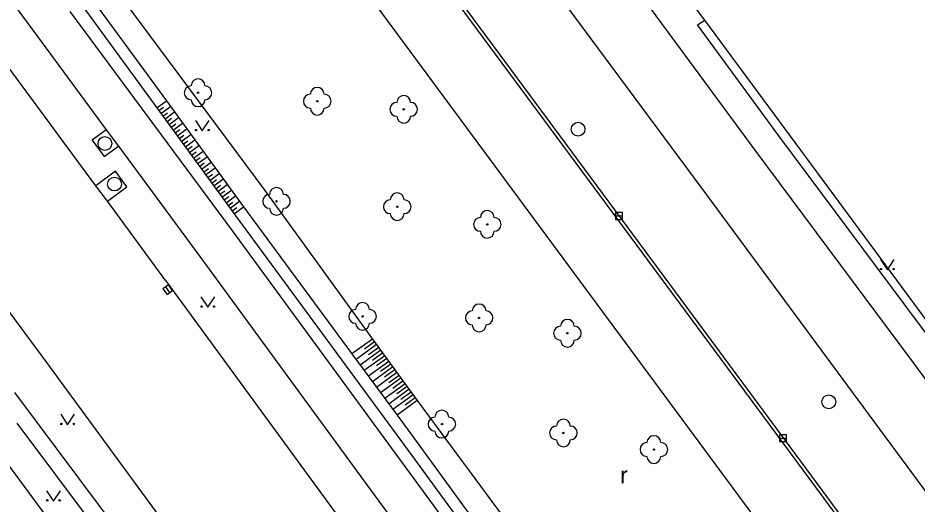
# Model space of a CAD drawing. Extents: x -596024 to -594475, y -1163820 to -1161957.
# Drawn here: x -594574.3 to -594509.2, y -1163261.3 to -1163226.1 of the extents above; entities that cross this region are included whole.
import ezdxf

# ---------------------------------------------------------------- set-up
doc = ezdxf.new("R2010")
doc.units = 0
for name, color, linetype in [('Level 10', 7, 'Continuous'), ('Level 11', 7, 'Continuous'), ('Level 14', 7, 'Continuous'), ('Level 15', 7, 'Continuous'), ('Level 22', 7, 'Continuous'), ('Level 27', 7, 'Continuous'), ('Level 36', 7, 'Continuous'), ('Level 5', 7, 'Continuous')]:
    doc.layers.add(name, color=color, linetype=linetype)

msp = doc.modelspace()

# ---------------------------------------------------------------- linework, layer by layer
at = {"layer": 'Level 10'}
for points in [[(-594476.38, -1163295.95), (-594483.21, -1163286.71), (-594496.95, -1163267.99), (-594509.44, -1163251.06), (-594520.92, -1163235.64), (-594534.84, -1163216.72), (-594549.23, -1163197.24), (-594565.49, -1163175.29), (-594578.05, -1163158.33), (-594594.16, -1163136.56), (-594607.21, -1163118.84), (-594619.14, -1163102.72), (-594629.15, -1163089.16), (-594640.89, -1163073.35), (-594644.69, -1163076.23)], [(-594568.65, -1163238.21), (-594575.33, -1163229.15)], [(-594583.7, -1163235.5), (-594572.22, -1163251)], [(-594567.81, -1163239.34), (-594568.65, -1163238.21)], [(-594563.57, -1163245.1), (-594567.81, -1163239.34)], [(-594563.57, -1163245.1), (-594551.26, -1163261.97)], [(-594572.22, -1163251), (-594559.99, -1163267.72)]]:
    msp.add_lwpolyline(points, dxfattribs=at)
at = {"layer": 'Level 11'}
for points in [[(-594658.25, -1163068.41), (-594648.78, -1163081.26), (-594637.52, -1163096.5), (-594627.94, -1163109.39), (-594616.36, -1163125.13), (-594603.5, -1163142.69), (-594587.25, -1163164.52), (-594574.42, -1163181.74), (-594559, -1163202.7), (-594543.73, -1163223.28), (-594530.41, -1163241.31), (-594518.2, -1163257.82), (-594506.57, -1163273.57), (-594492.81, -1163292.25), (-594492.53, -1163292.63), (-594483.61, -1163304.74), (-594481.85, -1163307.13)], [(-594657.91, -1163068.45), (-594648.58, -1163081.11), (-594637.31, -1163096.34), (-594627.74, -1163109.24), (-594616.16, -1163124.98), (-594603.29, -1163142.54), (-594587.04, -1163164.37), (-594574.22, -1163181.58), (-594558.79, -1163202.55), (-594543.52, -1163223.13), (-594530.21, -1163241.16), (-594518, -1163257.67), (-594506.37, -1163273.42), (-594492.33, -1163292.48), (-594481.65, -1163306.98), (-594481.85, -1163307.13)], [(-594496.66, -1163295.08), (-594662.09, -1163071.26)], [(-594480.26, -1163298.73), (-594487.23, -1163289.32), (-594500.98, -1163270.61), (-594513.05, -1163254.27), (-594524.82, -1163238.32), (-594538.75, -1163219.51), (-594553.56, -1163199.46), (-594569.42, -1163177.97), (-594581.93, -1163161.1), (-594598.22, -1163139.15), (-594611.25, -1163121.45), (-594623.1, -1163105.4), (-594630.38, -1163095.55), (-594644.69, -1163076.23)], [(-594584.79, -1163211.27), (-594572.88, -1163227.4)], [(-594570.52, -1163225.59), (-594558.76, -1163241.51)], [(-594502.96, -1163255.47), (-594503.48, -1163255.85), (-594507.9, -1163249.78), (-594519.28, -1163234.5), (-594525.1, -1163226.56), (-594524.57, -1163226.23)], [(-594572.88, -1163227.4), (-594567.89, -1163234.16)], [(-594567.89, -1163234.16), (-594568.91, -1163234.92)], [(-594567.89, -1163234.16), (-594567.02, -1163235.34)], [(-594568.91, -1163234.92), (-594568.05, -1163236.1)], [(-594568.05, -1163236.1), (-594567.02, -1163235.34)], [(-594567.02, -1163235.34), (-594561.12, -1163243.33)], [(-594567.22, -1163237.16), (-594568.65, -1163238.21)], [(-594566.4, -1163238.3), (-594567.22, -1163237.16)], [(-594567.81, -1163239.34), (-594566.4, -1163238.3)], [(-594558.76, -1163241.51), (-594546.73, -1163257.91)], [(-594561.12, -1163243.33), (-594549.02, -1163259.86)], [(-594546.73, -1163257.91), (-594534.76, -1163274.26)], [(-594549.02, -1163259.86), (-594538.3, -1163274.48)]]:
    msp.add_lwpolyline(points, dxfattribs=at)
at = {"layer": 'Level 14'}
for points in [[(-594570.38, -1163222.7), (-594563.54, -1163232.07), (-594557.95, -1163239.74)], [(-594568.3, -1163222.52), (-594556.42, -1163238.56)], [(-594569.79, -1163224.98), (-594564.24, -1163232.57), (-594558.63, -1163240.24)], [(-594556.42, -1163238.56), (-594548.61, -1163249.31), (-594545.38, -1163253.76)], [(-594558.63, -1163240.24), (-594546.04, -1163257.37)], [(-594557.95, -1163239.74), (-594550.11, -1163250.39), (-594546.84, -1163254.82)], [(-594562.25, -1163269.59), (-594574.52, -1163253.19)], [(-594545.38, -1163253.76), (-594532.52, -1163271.16)], [(-594546.84, -1163254.82), (-594545.38, -1163256.81)], [(-594574.36, -1163255.4), (-594563.25, -1163270.27)], [(-594576.23, -1163256.77), (-594565.21, -1163271.72)], [(-594545.38, -1163256.81), (-594538.57, -1163266.18), (-594534.16, -1163272.25)], [(-594546.04, -1163257.37), (-594539.25, -1163266.68), (-594534.83, -1163272.74)]]:
    msp.add_lwpolyline(points, dxfattribs=at)
at = {"layer": 'Level 15'}
for points in [[(-594564.24, -1163232.57), (-594563.54, -1163232.07)], [(-594564.09, -1163232.77), (-594563.74, -1163232.52)], [(-594563.94, -1163232.98), (-594563.25, -1163232.47)], [(-594563.8, -1163233.18), (-594563.45, -1163232.93)], [(-594563.65, -1163233.38), (-594562.95, -1163232.87)], [(-594563.5, -1163233.58), (-594563.16, -1163233.33)], [(-594563.35, -1163233.78), (-594562.66, -1163233.28)], [(-594563.21, -1163233.99), (-594562.86, -1163233.73)], [(-594563.06, -1163234.19), (-594562.37, -1163233.68)], [(-594562.91, -1163234.39), (-594562.56, -1163234.14)], [(-594562.76, -1163234.59), (-594562.07, -1163234.09)], [(-594562.47, -1163235), (-594561.78, -1163234.49)], [(-594562.62, -1163234.79), (-594562.27, -1163234.54)], [(-594562.32, -1163235.2), (-594561.98, -1163234.95)], [(-594562.17, -1163235.4), (-594561.48, -1163234.89)], [(-594562.03, -1163235.6), (-594561.68, -1163235.35)], [(-594561.88, -1163235.8), (-594561.19, -1163235.3)], [(-594561.73, -1163236), (-594561.39, -1163235.75)], [(-594561.58, -1163236.21), (-594560.89, -1163235.7)], [(-594561.44, -1163236.41), (-594561.09, -1163236.16)], [(-594561.29, -1163236.61), (-594560.6, -1163236.11)], [(-594561.14, -1163236.81), (-594560.8, -1163236.56)], [(-594560.99, -1163237.01), (-594560.3, -1163236.51)], [(-594560.85, -1163237.22), (-594560.5, -1163236.96)], [(-594560.7, -1163237.42), (-594560.01, -1163236.91)], [(-594560.55, -1163237.62), (-594560.21, -1163237.37)], [(-594560.4, -1163237.82), (-594559.72, -1163237.32)], [(-594560.26, -1163238.02), (-594559.91, -1163237.77)], [(-594560.11, -1163238.23), (-594559.42, -1163237.72)], [(-594559.96, -1163238.43), (-594559.62, -1163238.18)], [(-594559.81, -1163238.63), (-594559.13, -1163238.13)], [(-594559.67, -1163238.83), (-594559.32, -1163238.58)], [(-594559.52, -1163239.03), (-594558.83, -1163238.53)], [(-594559.37, -1163239.23), (-594559.03, -1163238.98)], [(-594559.22, -1163239.44), (-594558.54, -1163238.93)], [(-594559.07, -1163239.64), (-594558.73, -1163239.39)], [(-594558.93, -1163239.84), (-594558.24, -1163239.34)], [(-594558.78, -1163240.04), (-594558.44, -1163239.79)], [(-594558.63, -1163240.24), (-594557.95, -1163239.74)], [(-594548.61, -1163249.31), (-594550.11, -1163250.39)], [(-594548.32, -1163249.71), (-594549.81, -1163250.8)], [(-594548.02, -1163250.12), (-594549.51, -1163251.2)], [(-594548.47, -1163249.51), (-594549.21, -1163250.05)], [(-594548.17, -1163249.92), (-594548.92, -1163250.46)], [(-594547.73, -1163250.52), (-594549.22, -1163251.6)], [(-594547.88, -1163250.32), (-594548.62, -1163250.86)], [(-594547.58, -1163250.72), (-594548.33, -1163251.26)], [(-594547.44, -1163250.93), (-594548.92, -1163252)], [(-594547.14, -1163251.33), (-594548.62, -1163252.41)], [(-594547.29, -1163251.13), (-594548.03, -1163251.67)], [(-594546.85, -1163251.74), (-594548.33, -1163252.81)], [(-594547, -1163251.53), (-594547.74, -1163252.07)], [(-594546.7, -1163251.94), (-594547.44, -1163252.47)], [(-594546.56, -1163252.14), (-594548.03, -1163253.21)], [(-594546.26, -1163252.55), (-594547.73, -1163253.62)], [(-594546.41, -1163252.34), (-594547.15, -1163252.88)], [(-594545.97, -1163252.95), (-594547.44, -1163254.02)], [(-594545.67, -1163253.35), (-594547.14, -1163254.42)], [(-594546.11, -1163252.75), (-594546.85, -1163253.28)], [(-594545.82, -1163253.15), (-594546.56, -1163253.69)], [(-594545.38, -1163253.76), (-594546.84, -1163254.82)], [(-594545.53, -1163253.56), (-594546.26, -1163254.09)]]:
    msp.add_lwpolyline(points, dxfattribs=at)
at = {"layer": 'Level 22'}
for centre in [(-594561.25, -1163231.48), (-594552.62, -1163232.09), (-594546.36, -1163232.68), (-594555.57, -1163239.34), (-594546.83, -1163239.73), (-594540.31, -1163241.01), (-594549.34, -1163247.67), (-594540.9, -1163247.78), (-594534.51, -1163248.89), (-594543.6, -1163255.47), (-594534.8, -1163256.11), (-594528.25, -1163257.31)]:
    msp.add_circle(centre, 0.05, dxfattribs=at)
for centre, start, end in [((-594561.25, -1163230.98), 0, 180), ((-594561.75, -1163231.48), 90, 270), ((-594560.75, -1163231.48), 270, 90), ((-594552.62, -1163231.59), 0, 180), ((-594553.12, -1163232.09), 90, 270), ((-594552.12, -1163232.09), 270, 90), ((-594546.36, -1163232.18), 0, 180), ((-594561.25, -1163231.98), 180, 0), ((-594546.86, -1163232.68), 90, 270), ((-594545.86, -1163232.68), 270, 90), ((-594552.62, -1163232.59), 180, 0), ((-594546.36, -1163233.18), 180, 0), ((-594555.57, -1163238.84), 0, 180), ((-594556.07, -1163239.34), 90, 270), ((-594555.07, -1163239.34), 270, 90), ((-594546.83, -1163239.23), 0, 180), ((-594547.33, -1163239.73), 90, 270), ((-594546.33, -1163239.73), 270, 90), ((-594555.57, -1163239.84), 180, 0), ((-594546.83, -1163240.23), 180, 0), ((-594540.31, -1163240.51), 0, 180), ((-594540.81, -1163241.01), 90, 270), ((-594539.81, -1163241.01), 270, 90), ((-594540.31, -1163241.51), 180, 0), ((-594549.34, -1163247.17), 0, 180), ((-594540.9, -1163247.28), 0, 180), ((-594549.84, -1163247.67), 90, 270), ((-594548.84, -1163247.67), 270, 90), ((-594541.4, -1163247.78), 90, 270), ((-594540.4, -1163247.78), 270, 90), ((-594549.34, -1163248.17), 180, 0), ((-594534.51, -1163248.39), 0, 180), ((-594540.9, -1163248.28), 180, 0), ((-594535.01, -1163248.89), 90, 270), ((-594534.01, -1163248.89), 270, 90), ((-594534.51, -1163249.39), 180, 0), ((-594543.6, -1163254.97), 0, 180), ((-594544.1, -1163255.47), 90, 270), ((-594543.1, -1163255.47), 270, 90), ((-594534.8, -1163255.61), 0, 180), ((-594543.6, -1163255.97), 180, 0), ((-594535.3, -1163256.11), 90, 270), ((-594534.3, -1163256.11), 270, 90), ((-594534.8, -1163256.61), 180, 0), ((-594528.25, -1163256.81), 0, 180), ((-594528.75, -1163257.31), 90, 270), ((-594527.75, -1163257.31), 270, 90), ((-594528.25, -1163257.81), 180, 0)]:
    msp.add_arc(centre, 0.5, start, end, dxfattribs=at)
at = {"layer": 'Level 27'}
for p, q in [((-594531.02, -1163240.4), (-594530.52, -1163240.4)), ((-594563.293, -1163245.932), (-594563.587, -1163245.528)), ((-594519.15, -1163256.49), (-594518.65, -1163256.49))]:
    msp.add_line(p, q, dxfattribs=at)
for points in [[(-594531.02, -1163240.65), (-594530.52, -1163240.65), (-594530.52, -1163240.15), (-594531.02, -1163240.15)], [(-594563.091, -1163245.785), (-594563.385, -1163245.381), (-594563.789, -1163245.675), (-594563.495, -1163246.079)], [(-594519.15, -1163256.74), (-594518.65, -1163256.74), (-594518.65, -1163256.24), (-594519.15, -1163256.24)]]:
    msp.add_lwpolyline(points, close=True, dxfattribs=at)
for centre in [(-594533.74, -1163234.12), (-594567.99, -1163235.15), (-594567.3, -1163238.09), (-594515.59, -1163253.86)]:
    msp.add_circle(centre, 0.5, dxfattribs=at)
at = {"layer": 'Level 36'}
for points in [[(-594561.44, -1163233.48), (-594560.94, -1163234.23), (-594560.44, -1163233.48)], [(-594511.85, -1163243.55), (-594511.35, -1163244.3), (-594510.85, -1163243.55)], [(-594561.04, -1163246.26), (-594560.54, -1163247.01), (-594560.04, -1163246.26)], [(-594571.19, -1163254.76), (-594570.69, -1163255.51), (-594570.19, -1163254.76)], [(-594572.21, -1163260.29), (-594571.71, -1163261.04), (-594571.21, -1163260.29)]]:
    msp.add_lwpolyline(points, dxfattribs=at)
for centre in [(-594561.39, -1163234.18), (-594560.491, -1163234.18), (-594511.8, -1163244.25), (-594510.901, -1163244.25), (-594560.99, -1163246.96), (-594560.091, -1163246.96), (-594571.14, -1163255.46), (-594570.241, -1163255.46), (-594572.16, -1163260.99), (-594571.261, -1163260.99)]:
    msp.add_circle(centre, 0.05, dxfattribs=at)
at = {"layer": 'Level 5'}
for points in [[(-594524.57, -1163226.23), (-594525.78, -1163224.6)], [(-594502.96, -1163255.47), (-594524.57, -1163226.23)]]:
    msp.add_lwpolyline(points, dxfattribs=at)

# ---------------------------------------------------------------- texts
at = {"layer": 'Level 36'}
msp.add_text('r', height=1.2, dxfattribs=at).set_placement((-594530.683, -1163259.757))

doc.saveas('drawing.dxf')
